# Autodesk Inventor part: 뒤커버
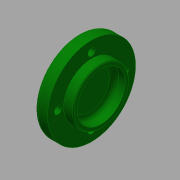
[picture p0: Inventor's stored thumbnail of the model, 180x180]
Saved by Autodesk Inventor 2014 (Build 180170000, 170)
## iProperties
Created: 2015-12
Part Number: 뒤커버
Material: 일반
Document SubType Name: Modeling
Designer: mduedu
Density: 1 g/cm^3
Appearance: Dark Green
Author: mduedu
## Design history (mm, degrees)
sketch "스케치1"
  geometry: L1 (0, 0)-(14, 0); L2 (14, 0)-(14, 17.5); L3 (14, 17.5)-(8, 17.5); L4 (8, 17.5)-(8, 27.5); L5 (8, 27.5)-(0, 27.5); L6 (0, 27.5)-(0, 0)
  constraints: 12 end point, 4 parallel, 1 horizontal, 1 perpendicular
  dimensions: "d0" = 14 distance between parallel lines of L2 L6; "d2" = 8 distance of L4.end L5.end; "d3" = 55 diameter of L5 L1; "d4" = 35 diameter of L3 L1
revolve "회전1" sketch "스케치1" stored, may be unused: angle "d5" = 90 deg
hole "구멍1" diameter "d8" = 30; stored, may be unused: countersink angle "d12" = 90 deg, drill point angle "d14" = 0 deg; dims "d9" = 6, "d10" = 4, "d11" = 2, "d13" = 7, "d39" = 10, "d40" = 10
fillet "모깎기3" dims "d38" = 2
fillet "모깎기4" dims "d41" = 3
chamfer "모따기2" distance "d42" = 0.5; stored, may be unused: second distance "d43" = 2, angle "d44" = 45 deg
sketch "스케치2" dims "d45" = 42
  geometry: 6 further points
  constraints: 2 vertical alignment, 1 coincident, 7 other
  dimensions: "d48" = 360 deg dimension on point (0, 0) point (0, 21) (derived)
sketch "스케치3"
  geometry: 4 further points
hole "구멍4" sketch "스케치3" at (-21, 0), (0, -21), (21, 0), (0, 21) diameter "d50" = 4.5; stored, may be unused: countersink angle "d54" = 90 deg, drill point angle "d56" = 0 deg; dims "d51" = 6, "d52" = 8, "d53" = 4.6, "d55" = 8
node "솔리드1"
